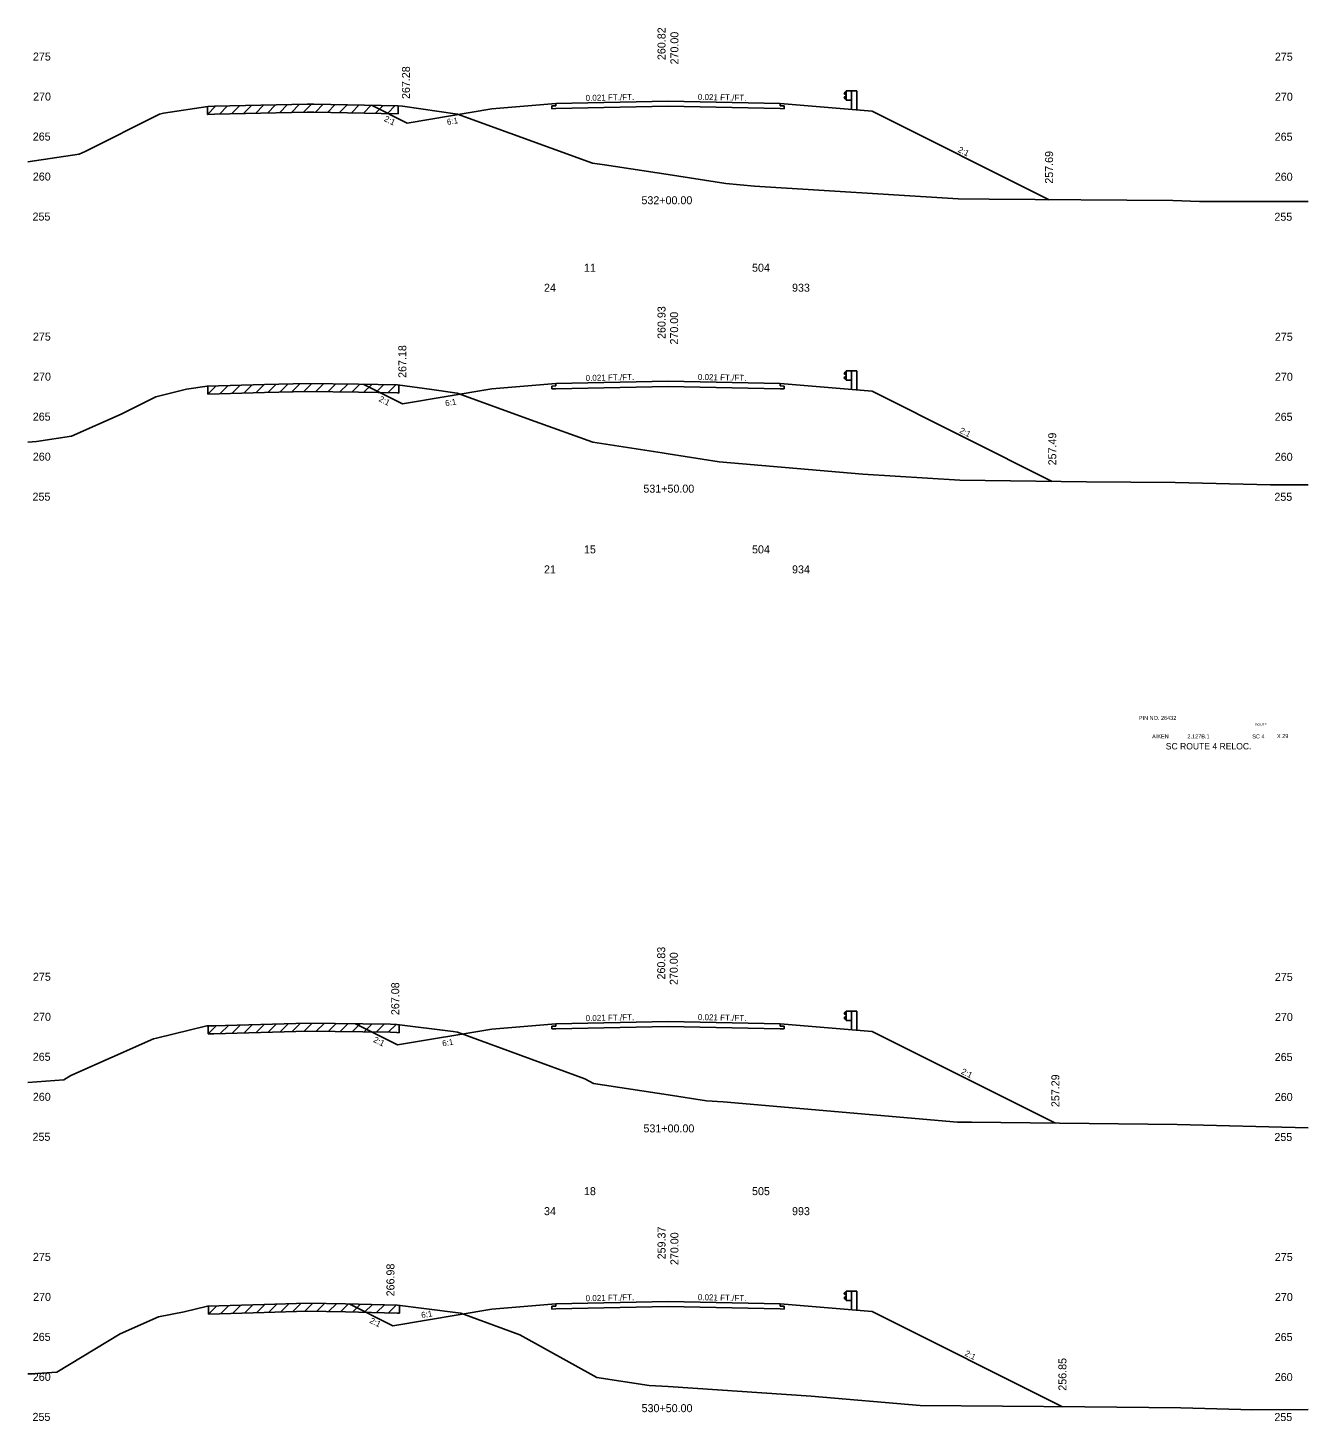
# Model space of a CAD drawing. Extents: x 2967 to 4323, y -3677 to -817.
# Drawn here: x 3555.3 to 3715.3, y -3319.8 to -3145.7 of the extents above; entities that cross this region are included whole.
import ezdxf

# ---------------------------------------------------------------- set-up
doc = ezdxf.new("R2010")
doc.units = 0
for name, color, linetype in [('Level 1', 7, 'Continuous'), ('Level 10', 7, 'Continuous'), ('Level 11', 7, 'Continuous'), ('Level 12', 7, 'Continuous'), ('Level 20', 7, 'Continuous'), ('Level 24', 7, 'Continuous'), ('Level 3', 7, 'Continuous'), ('Level 32', 7, 'Continuous'), ('Level 33', 7, 'Continuous'), ('Level 59', 7, 'Continuous'), ('Level 6', 7, 'Continuous'), ('Level 60', 7, 'Continuous'), ('Level 61', 7, 'Continuous'), ('Level 7', 7, 'Continuous')]:
    doc.layers.add(name, color=color, linetype=linetype)

msp = doc.modelspace()

# ---------------------------------------------------------------- linework, layer by layer
at = {"layer": 'Level 11'}
for p, q in [((3621.35, -3155.43), (3620.85, -3155.44)), ((3620.85, -3155.44), (3620.85, -3155.78)), ((3620.85, -3155.78), (3621.35, -3155.77)), ((3621.35, -3155.13), (3621.35, -3155.43)), ((3649.35, -3155.43), (3649.35, -3155.13)), ((3649.85, -3155.44), (3649.35, -3155.43)), ((3649.35, -3155.77), (3649.85, -3155.78)), ((3649.85, -3155.78), (3649.85, -3155.44)), ((3621.35, -3190.43), (3620.85, -3190.44)), ((3620.85, -3190.44), (3620.85, -3190.78)), ((3620.85, -3190.78), (3621.35, -3190.77)), ((3621.35, -3190.13), (3621.35, -3190.43)), ((3649.35, -3190.43), (3649.35, -3190.13)), ((3649.85, -3190.44), (3649.35, -3190.43)), ((3649.35, -3190.77), (3649.85, -3190.78)), ((3649.85, -3190.78), (3649.85, -3190.44)), ((3621.35, -3270.43), (3620.85, -3270.44)), ((3620.85, -3270.44), (3620.85, -3270.78)), ((3620.85, -3270.78), (3621.35, -3270.77)), ((3621.35, -3270.13), (3621.35, -3270.43)), ((3649.35, -3270.43), (3649.35, -3270.13)), ((3649.85, -3270.44), (3649.35, -3270.43)), ((3649.35, -3270.77), (3649.85, -3270.78)), ((3649.85, -3270.78), (3649.85, -3270.44)), ((3621.35, -3305.43), (3620.85, -3305.44)), ((3620.85, -3305.44), (3620.85, -3305.78)), ((3620.85, -3305.78), (3621.35, -3305.77)), ((3621.35, -3305.13), (3621.35, -3305.43)), ((3649.35, -3305.43), (3649.35, -3305.13)), ((3649.85, -3305.44), (3649.35, -3305.43)), ((3649.35, -3305.77), (3649.85, -3305.78)), ((3649.85, -3305.78), (3649.85, -3305.44))]:
    msp.add_line(p, q, dxfattribs=at)
at = {"layer": 'Level 12'}
for p, q in [((3635.35, -3155.48), (3621.35, -3155.77)), ((3649.35, -3155.77), (3635.35, -3155.48)), ((3635.35, -3190.48), (3621.35, -3190.77)), ((3649.35, -3190.77), (3635.35, -3190.48)), ((3635.35, -3270.48), (3621.35, -3270.77)), ((3649.35, -3270.77), (3635.35, -3270.48)), ((3635.35, -3305.48), (3621.35, -3305.77)), ((3649.35, -3305.77), (3635.35, -3305.48))]:
    msp.add_line(p, q, dxfattribs=at)
at = {"layer": 'Level 24'}
for p, q in [((3657.62, -3153.62), (3657.35, -3153.82)), ((3657.35, -3153.82), (3657.35, -3153.87)), ((3657.35, -3153.87), (3657.62, -3154.07)), ((3657.35, -3154.39), (3657.62, -3154.19)), ((3657.35, -3154.44), (3657.35, -3154.39)), ((3657.62, -3154.64), (3657.35, -3154.44)), ((3657.62, -3154.72), (3657.62, -3153.55)), ((3657.62, -3153.55), (3658.28, -3153.55)), ((3657.62, -3154.72), (3658.29, -3154.72)), ((3658.28, -3153.55), (3658.28, -3155.88)), ((3658.28, -3153.55), (3658.95, -3153.55)), ((3658.95, -3153.55), (3658.95, -3155.93)), ((3657.62, -3188.62), (3657.35, -3188.82)), ((3657.35, -3188.82), (3657.35, -3188.87)), ((3657.35, -3188.87), (3657.62, -3189.07)), ((3657.35, -3189.39), (3657.62, -3189.19)), ((3657.35, -3189.44), (3657.35, -3189.39)), ((3657.62, -3189.64), (3657.35, -3189.44)), ((3657.62, -3189.72), (3657.62, -3188.55)), ((3657.62, -3188.55), (3658.28, -3188.55)), ((3657.62, -3189.72), (3658.29, -3189.72)), ((3658.28, -3188.55), (3658.28, -3190.88)), ((3658.28, -3188.55), (3658.95, -3188.55)), ((3658.95, -3188.55), (3658.95, -3190.93)), ((3657.62, -3268.62), (3657.35, -3268.82)), ((3657.35, -3268.82), (3657.35, -3268.87)), ((3657.35, -3268.87), (3657.62, -3269.07)), ((3657.35, -3269.39), (3657.62, -3269.19)), ((3657.35, -3269.44), (3657.35, -3269.39)), ((3657.62, -3269.64), (3657.35, -3269.44)), ((3657.62, -3269.72), (3657.62, -3268.55)), ((3657.62, -3268.55), (3658.28, -3268.55)), ((3657.62, -3269.72), (3658.29, -3269.72)), ((3658.28, -3268.55), (3658.28, -3270.88)), ((3658.28, -3268.55), (3658.95, -3268.55)), ((3658.95, -3268.55), (3658.95, -3270.93)), ((3657.62, -3303.62), (3657.35, -3303.82)), ((3657.35, -3303.82), (3657.35, -3303.87)), ((3657.35, -3303.87), (3657.62, -3304.07)), ((3657.35, -3304.39), (3657.62, -3304.19)), ((3657.35, -3304.44), (3657.35, -3304.39)), ((3657.62, -3304.64), (3657.35, -3304.44)), ((3657.62, -3304.72), (3657.62, -3303.55)), ((3657.62, -3303.55), (3658.28, -3303.55)), ((3658.28, -3303.55), (3658.28, -3305.88)), ((3658.28, -3303.55), (3658.95, -3303.55)), ((3658.95, -3303.55), (3658.95, -3305.93)), ((3657.62, -3304.72), (3658.29, -3304.72))]:
    msp.add_line(p, q, dxfattribs=at)
at = {"layer": 'Level 59'}
for p, q in [((3621.35, -3155.13), (3635.35, -3154.84)), ((3635.35, -3154.84), (3649.35, -3155.13)), ((3621.35, -3190.13), (3635.35, -3189.84)), ((3635.35, -3189.84), (3649.35, -3190.13)), ((3621.35, -3270.13), (3635.35, -3269.84)), ((3635.35, -3269.84), (3649.35, -3270.13)), ((3621.35, -3305.13), (3635.35, -3304.84)), ((3635.35, -3304.84), (3649.35, -3305.13))]:
    msp.add_line(p, q, dxfattribs=at)
at = {"layer": 'Level 6'}
for p, q in [((3613.35, -3155.8), (3621.35, -3155.13)), ((3649.35, -3155.13), (3657.35, -3155.8)), ((3657.35, -3155.8), (3660.85, -3156.09)), ((3613.35, -3190.8), (3621.35, -3190.13)), ((3649.35, -3190.13), (3657.35, -3190.8)), ((3657.35, -3190.8), (3660.85, -3191.09)), ((3613.35, -3270.8), (3621.35, -3270.13)), ((3649.35, -3270.13), (3657.35, -3270.8)), ((3657.35, -3270.8), (3660.85, -3271.09)), ((3613.35, -3305.8), (3621.35, -3305.13)), ((3649.35, -3305.13), (3657.35, -3305.8)), ((3657.35, -3305.8), (3660.85, -3306.09))]:
    msp.add_line(p, q, dxfattribs=at)
at = {"layer": 'Level 60'}
for p, q in [((3562.49, -3161.11), (3571.81, -3156.45)), ((3571.81, -3156.45), (3572.28, -3156.33)), ((3572.28, -3156.33), (3577.82, -3155.5)), ((3577.82, -3155.5), (3578.69, -3155.48)), ((3578.69, -3155.48), (3590.27, -3155.2)), ((3590.27, -3155.2), (3591.07, -3155.21)), ((3591.07, -3155.21), (3601.63, -3155.4)), ((3601.63, -3155.4), (3602.18, -3155.47)), ((3602.18, -3155.47), (3609.04, -3156.47)), ((3609.04, -3156.47), (3610.41, -3156.97)), ((3610.41, -3156.97), (3625.92, -3162.57)), ((3555.35, -3162.4), (3561.75, -3161.44)), ((3561.75, -3161.44), (3562.49, -3161.11)), ((3625.92, -3162.57), (3627.4, -3162.8)), ((3627.4, -3162.8), (3635.35, -3164.02)), ((3635.35, -3164.02), (3642.56, -3165.13)), ((3642.56, -3165.13), (3646.16, -3165.45)), ((3646.16, -3165.45), (3671.61, -3167.05)), ((3671.61, -3167.05), (3675.48, -3167.09)), ((3675.48, -3167.09), (3698.44, -3167.27)), ((3698.44, -3167.27), (3701.79, -3167.36)), ((3701.79, -3167.36), (3715.35, -3167.37)), ((3571.36, -3191.77), (3575.19, -3190.83)), ((3575.19, -3190.83), (3577.75, -3190.45)), ((3577.75, -3190.45), (3584.93, -3190.24)), ((3584.93, -3190.24), (3590.29, -3190.11)), ((3590.29, -3190.11), (3596.66, -3190.21)), ((3596.66, -3190.21), (3601.53, -3190.29)), ((3601.53, -3190.29), (3605.85, -3190.85)), ((3605.85, -3190.85), (3609.02, -3191.31)), ((3609.02, -3191.31), (3618.73, -3194.86)), ((3567.02, -3193.94), (3571.36, -3191.77)), ((3560.8, -3196.71), (3567.02, -3193.94)), ((3618.73, -3194.86), (3625.96, -3197.47)), ((3556.44, -3197.37), (3560.8, -3196.71)), ((3555.35, -3197.44), (3556.44, -3197.37)), ((3625.96, -3197.47), (3634.61, -3198.8)), ((3634.61, -3198.8), (3635.35, -3198.91)), ((3635.35, -3198.91), (3641.73, -3199.89)), ((3641.73, -3199.89), (3659.7, -3201.46)), ((3659.7, -3201.46), (3671.8, -3202.22)), ((3671.8, -3202.22), (3687.67, -3202.4)), ((3687.67, -3202.4), (3698.71, -3202.49)), ((3698.71, -3202.49), (3710.63, -3202.78)), ((3710.63, -3202.78), (3715.35, -3202.79)), ((3571.42, -3271.95), (3577.71, -3270.41)), ((3577.71, -3270.41), (3578.57, -3270.38)), ((3578.57, -3270.38), (3590.29, -3270.05)), ((3590.29, -3270.05), (3600.65, -3270.19)), ((3600.65, -3270.19), (3601.47, -3270.21)), ((3601.47, -3270.21), (3608.5, -3271.12)), ((3608.5, -3271.12), (3609.06, -3271.2)), ((3609.06, -3271.2), (3624.97, -3277)), ((3560.73, -3276.61), (3571.04, -3272.02)), ((3571.04, -3272.02), (3571.42, -3271.95)), ((3559.86, -3277.14), (3560.73, -3276.61)), ((3555.35, -3277.46), (3559.86, -3277.14)), ((3624.97, -3277), (3626.05, -3277.6)), ((3626.05, -3277.6), (3635.35, -3279.01)), ((3635.35, -3279.01), (3640.16, -3279.75)), ((3640.16, -3279.75), (3642.26, -3279.89)), ((3642.26, -3279.89), (3671.53, -3282.42)), ((3671.53, -3282.42), (3673.29, -3282.44)), ((3673.29, -3282.44), (3698.99, -3282.71)), ((3698.99, -3282.71), (3715.35, -3283.12)), ((3571.66, -3306.76), (3574.9, -3306.15)), ((3574.9, -3306.15), (3577.8, -3305.44)), ((3577.8, -3305.44), (3584.86, -3305.22)), ((3584.86, -3305.22), (3590.27, -3305.07)), ((3590.27, -3305.07), (3595.05, -3305.14)), ((3595.05, -3305.14), (3601.56, -3305.28)), ((3601.56, -3305.28), (3604.82, -3305.7)), ((3604.82, -3305.7), (3609.46, -3306.31)), ((3609.46, -3306.31), (3616.82, -3309)), ((3566.9, -3308.88), (3571.66, -3306.76)), ((3558.98, -3313.69), (3566.9, -3308.88)), ((3616.82, -3309), (3626.45, -3314.32)), ((3555.35, -3313.9), (3555.92, -3313.9)), ((3555.92, -3313.9), (3558.98, -3313.69)), ((3626.45, -3314.32), (3632.99, -3315.32)), ((3632.99, -3315.32), (3635.35, -3315.48)), ((3635.35, -3315.48), (3653.26, -3316.67)), ((3653.26, -3316.67), (3666.86, -3317.84)), ((3666.86, -3317.84), (3687.45, -3318.01)), ((3687.45, -3318.01), (3699.42, -3318.14)), ((3699.42, -3318.14), (3708.44, -3318.36)), ((3708.44, -3318.36), (3715.35, -3318.33))]:
    msp.add_line(p, q, dxfattribs=at)
at = {"layer": 'Level 61'}
for p, q in [((3578.81, -3155.48), (3577.78, -3156.51)), ((3577.78, -3155.51), (3577.78, -3156.51)), ((3577.78, -3156.51), (3577.82, -3156.5)), ((3577.82, -3156.5), (3578.69, -3156.48)), ((3578.69, -3156.48), (3590.27, -3156.2)), ((3580.31, -3155.44), (3579.28, -3156.46)), ((3581.81, -3155.4), (3580.78, -3156.43)), ((3583.31, -3155.37), (3582.28, -3156.39)), ((3584.81, -3155.33), (3583.78, -3156.36)), ((3586.31, -3155.3), (3585.28, -3156.32)), ((3587.81, -3155.26), (3586.78, -3156.28)), ((3589.31, -3155.22), (3588.28, -3156.25)), ((3590.78, -3155.21), (3589.78, -3156.21)), ((3590.27, -3156.2), (3591.07, -3156.21)), ((3591.07, -3156.21), (3601.63, -3156.4)), ((3592.26, -3155.23), (3591.28, -3156.21)), ((3593.76, -3155.26), (3592.78, -3156.24)), ((3595.26, -3155.28), (3594.28, -3156.27)), ((3596.76, -3155.31), (3595.78, -3156.29)), ((3598.26, -3155.34), (3597.28, -3156.32)), ((3599.76, -3155.36), (3598.78, -3156.35)), ((3601.26, -3155.39), (3600.28, -3156.37)), ((3601.63, -3156.4), (3601.64, -3156.4)), ((3601.64, -3156.4), (3601.64, -3155.4)), ((3578.87, -3190.42), (3577.84, -3191.45)), ((3577.84, -3190.45), (3577.84, -3191.45)), ((3577.84, -3191.45), (3584.93, -3191.24)), ((3580.37, -3190.37), (3579.34, -3191.4)), ((3581.87, -3190.33), (3580.84, -3191.36)), ((3583.37, -3190.29), (3582.34, -3191.32)), ((3584.87, -3190.25), (3583.84, -3191.28)), ((3584.93, -3191.24), (3590.29, -3191.11)), ((3586.37, -3190.21), (3585.34, -3191.23)), ((3587.87, -3190.17), (3586.84, -3191.2)), ((3589.37, -3190.14), (3588.34, -3191.16)), ((3590.84, -3190.12), (3589.84, -3191.13)), ((3590.29, -3191.11), (3596.66, -3191.21)), ((3592.33, -3190.14), (3591.34, -3191.13)), ((3593.83, -3190.17), (3592.84, -3191.15)), ((3595.33, -3190.19), (3594.34, -3191.17)), ((3596.83, -3190.21), (3595.84, -3191.19)), ((3596.66, -3191.21), (3601.53, -3191.29)), ((3598.32, -3190.24), (3597.34, -3191.22)), ((3599.82, -3190.26), (3598.84, -3191.24)), ((3601.32, -3190.29), (3600.34, -3191.27)), ((3601.53, -3191.29), (3601.69, -3191.31)), ((3601.69, -3191.31), (3601.69, -3190.31)), ((3578.92, -3270.37), (3577.88, -3271.4)), ((3577.88, -3270.4), (3577.88, -3271.4)), ((3577.88, -3271.4), (3578.57, -3271.38)), ((3578.57, -3271.38), (3590.29, -3271.05)), ((3580.41, -3270.33), (3579.38, -3271.36)), ((3581.91, -3270.28), (3580.88, -3271.31)), ((3583.41, -3270.24), (3582.38, -3271.27)), ((3584.91, -3270.2), (3583.88, -3271.23)), ((3586.41, -3270.16), (3585.38, -3271.19)), ((3587.91, -3270.11), (3586.88, -3271.14)), ((3589.41, -3270.07), (3588.38, -3271.1)), ((3590.89, -3270.05), (3589.88, -3271.06)), ((3590.29, -3271.05), (3600.65, -3271.19)), ((3592.37, -3270.08), (3591.38, -3271.06)), ((3593.87, -3270.1), (3592.88, -3271.08)), ((3595.37, -3270.12), (3594.38, -3271.1)), ((3596.87, -3270.14), (3595.88, -3271.13)), ((3598.37, -3270.16), (3597.38, -3271.15)), ((3599.87, -3270.18), (3598.88, -3271.17)), ((3601.37, -3270.21), (3600.38, -3271.19)), ((3600.65, -3271.19), (3601.47, -3271.21)), ((3601.47, -3271.21), (3601.74, -3271.25)), ((3601.74, -3271.25), (3601.74, -3270.25)), ((3578.96, -3305.4), (3577.93, -3306.43)), ((3577.93, -3305.43), (3577.93, -3306.43)), ((3577.93, -3306.43), (3584.86, -3306.22)), ((3580.46, -3305.36), (3579.43, -3306.39)), ((3581.96, -3305.31), (3580.93, -3306.34)), ((3583.46, -3305.27), (3582.43, -3306.3)), ((3584.96, -3305.22), (3583.93, -3306.25)), ((3584.86, -3306.22), (3590.27, -3306.07)), ((3586.46, -3305.18), (3585.43, -3306.21)), ((3587.96, -3305.14), (3586.93, -3306.17)), ((3589.46, -3305.09), (3588.43, -3306.12)), ((3590.93, -3305.08), (3589.93, -3306.08)), ((3590.27, -3306.07), (3595.05, -3306.14)), ((3592.41, -3305.1), (3591.43, -3306.09)), ((3593.91, -3305.12), (3592.93, -3306.11)), ((3595.41, -3305.15), (3594.43, -3306.13)), ((3595.05, -3306.14), (3601.56, -3306.28)), ((3596.91, -3305.18), (3595.93, -3306.16)), ((3598.41, -3305.21), (3597.43, -3306.19)), ((3599.91, -3305.24), (3598.93, -3306.22)), ((3601.41, -3305.27), (3600.43, -3306.25)), ((3601.56, -3306.28), (3601.78, -3306.3)), ((3601.78, -3306.3), (3601.78, -3305.3))]:
    msp.add_line(p, q, dxfattribs=at)
at = {"layer": 'Level 7'}
for p, q in [((3598.29, -3155.34), (3602.75, -3157.57)), ((3602.75, -3157.57), (3613.35, -3155.8)), ((3660.85, -3156.09), (3682.97, -3167.15)), ((3597.24, -3190.21), (3602.15, -3192.67)), ((3602.15, -3192.67), (3613.35, -3190.8)), ((3660.85, -3191.09), (3683.37, -3202.35)), ((3596.28, -3270.13), (3601.55, -3272.77)), ((3601.55, -3272.77), (3613.35, -3270.8)), ((3660.85, -3271.09), (3683.76, -3282.55)), ((3595.51, -3305.15), (3600.95, -3307.87)), ((3600.95, -3307.87), (3613.35, -3305.8)), ((3660.85, -3306.09), (3684.64, -3317.99))]:
    msp.add_line(p, q, dxfattribs=at)

# ---------------------------------------------------------------- texts
at = {"layer": 'Level 1'}
for s, p in [('11', (3624.85, -3176.15)), ('504', (3645.85, -3176.15)), ('24', (3619.85, -3178.65)), ('933', (3650.85, -3178.65)), ('15', (3624.85, -3211.35)), ('504', (3645.85, -3211.35)), ('21', (3619.85, -3213.85)), ('934', (3650.85, -3213.85)), ('18', (3624.85, -3291.55)), ('505', (3645.85, -3291.55)), ('34', (3619.85, -3294.05)), ('993', (3650.85, -3294.05))]:
    msp.add_text(s, height=1, dxfattribs=at).set_placement(p)
at = {"layer": 'Level 10'}
for s, p in [('260.82', (3635.04, -3149.7)), ('260.93', (3635.04, -3184.55)), ('260.83', (3635, -3264.6)), ('259.37', (3635.04, -3299.57))]:
    msp.add_text(s, height=1, rotation=90, dxfattribs=at).set_placement(p)
for s, p in [('532+00.00', (3632.03, -3167.72)), ('531+50.00', (3632.27, -3203.76)), ('531+00.00', (3632.28, -3283.71)), ('530+50.00', (3632.05, -3318.67))]:
    msp.add_text(s, height=1, dxfattribs=at).set_placement(p)
at = {"layer": 'Level 20'}
for s, height, p in [('PIN NO. 26432', 0.5, (3694.19, -3232.16)), ('ROUTE', 0.3, (3708.73, -3232.9)), ('AIKEN', 0.5, (3695.85, -3234.47)), ('SC ROUTE 4 RELOC.', 0.8, (3697.56, -3235.85)), (' 2.127B.1', 0.5, (3700.07, -3234.47)), ('SC 4', 0.5, (3708.36, -3234.47)), ('X 29', 0.5, (3711.45, -3234.43))]:
    msp.add_text(s, height=height, dxfattribs=at).set_placement(p)
at = {"layer": 'Level 3'}
for s, p in [(' 275', (3555.61, -3149.76)), (' 275', (3710.82, -3149.78)), (' 270', (3555.63, -3154.76)), (' 270', (3710.83, -3154.78)), (' 265', (3555.59, -3159.76)), (' 265', (3710.8, -3159.78)), (' 260', (3555.6, -3164.76)), (' 260', (3710.81, -3164.78)), (' 255', (3555.56, -3169.76)), (' 255', (3710.76, -3169.78)), (' 275', (3555.61, -3184.76)), (' 275', (3710.82, -3184.78)), (' 270', (3555.63, -3189.76)), (' 270', (3710.83, -3189.78)), (' 265', (3555.59, -3194.76)), (' 265', (3710.8, -3194.78)), (' 260', (3555.6, -3199.76)), (' 260', (3710.81, -3199.78)), (' 255', (3555.56, -3204.76)), (' 255', (3710.76, -3204.78)), (' 275', (3555.61, -3264.76)), (' 275', (3710.82, -3264.78)), (' 270', (3555.63, -3269.76)), (' 270', (3710.83, -3269.78)), (' 265', (3555.59, -3274.76)), (' 265', (3710.8, -3274.78)), (' 260', (3555.6, -3279.76)), (' 260', (3710.81, -3279.78)), (' 255', (3555.56, -3284.76)), (' 255', (3710.76, -3284.78)), (' 275', (3555.61, -3299.76)), (' 275', (3710.82, -3299.78)), (' 270', (3555.63, -3304.76)), (' 270', (3710.83, -3304.78)), (' 265', (3555.59, -3309.76)), (' 265', (3710.8, -3309.78)), (' 260', (3555.6, -3314.76)), (' 260', (3710.81, -3314.78)), (' 255', (3555.56, -3319.76)), (' 255', (3710.76, -3319.78))]:
    msp.add_text(s, height=1, dxfattribs=at).set_placement(p)
at = {"layer": 'Level 32'}
for s, rotation, p in [('0.021 FT./FT.', 1.1916, (3625.06, -3154.81)), ('0.021 FT./FT.', 358.8084, (3639.07, -3154.67)), ('2:1', 333.435, (3599.79, -3157.28)), ('6:1', 9.4623, (3607.78, -3157.82)), ('2:1', 333.435, (3671.51, -3161.14)), ('0.021 FT./FT.', 1.1916, (3625.06, -3189.81)), ('0.021 FT./FT.', 358.8084, (3639.07, -3189.67)), ('2:1', 333.435, (3599.13, -3192.3)), ('6:1', 9.4623, (3607.56, -3192.97)), ('2:1', 333.435, (3671.71, -3196.24)), ('0.021 FT./FT.', 1.1916, (3625.06, -3269.81)), ('0.021 FT./FT.', 358.8084, (3639.07, -3269.67)), ('2:1', 333.435, (3598.45, -3272.37)), ('6:1', 9.4623, (3607.19, -3272.97)), ('2:1', 333.435, (3671.91, -3276.34)), ('0.021 FT./FT.', 1.1916, (3625.06, -3304.81)), ('0.021 FT./FT.', 358.8084, (3639.07, -3304.67)), ('6:1', 9.4623, (3604.57, -3306.92)), ('2:1', 333.435, (3597.98, -3307.47)), ('2:1', 333.435, (3672.35, -3311.56))]:
    msp.add_text(s, height=0.75, rotation=rotation, dxfattribs=at).set_placement(p)
at = {"layer": 'Level 33'}
for s, p in [('267.28', (3603.1, -3154.57)), ('257.69', (3683.47, -3165.15)), ('267.18', (3602.65, -3189.42)), ('257.49', (3683.87, -3200.35)), ('267.08', (3601.76, -3269.05)), ('257.29', (3684.26, -3280.55)), ('266.98', (3601.16, -3304.2)), ('256.85', (3685.14, -3315.99))]:
    msp.add_text(s, height=1, rotation=90, dxfattribs=at).set_placement(p)
at = {"layer": 'Level 59'}
for p in [(3636.65, -3150.62), (3636.61, -3185.62), (3636.57, -3265.66), (3636.65, -3300.66)]:
    msp.add_text(' 270.00', height=1, rotation=90, dxfattribs=at).set_placement(p)

doc.saveas('drawing.dxf')
